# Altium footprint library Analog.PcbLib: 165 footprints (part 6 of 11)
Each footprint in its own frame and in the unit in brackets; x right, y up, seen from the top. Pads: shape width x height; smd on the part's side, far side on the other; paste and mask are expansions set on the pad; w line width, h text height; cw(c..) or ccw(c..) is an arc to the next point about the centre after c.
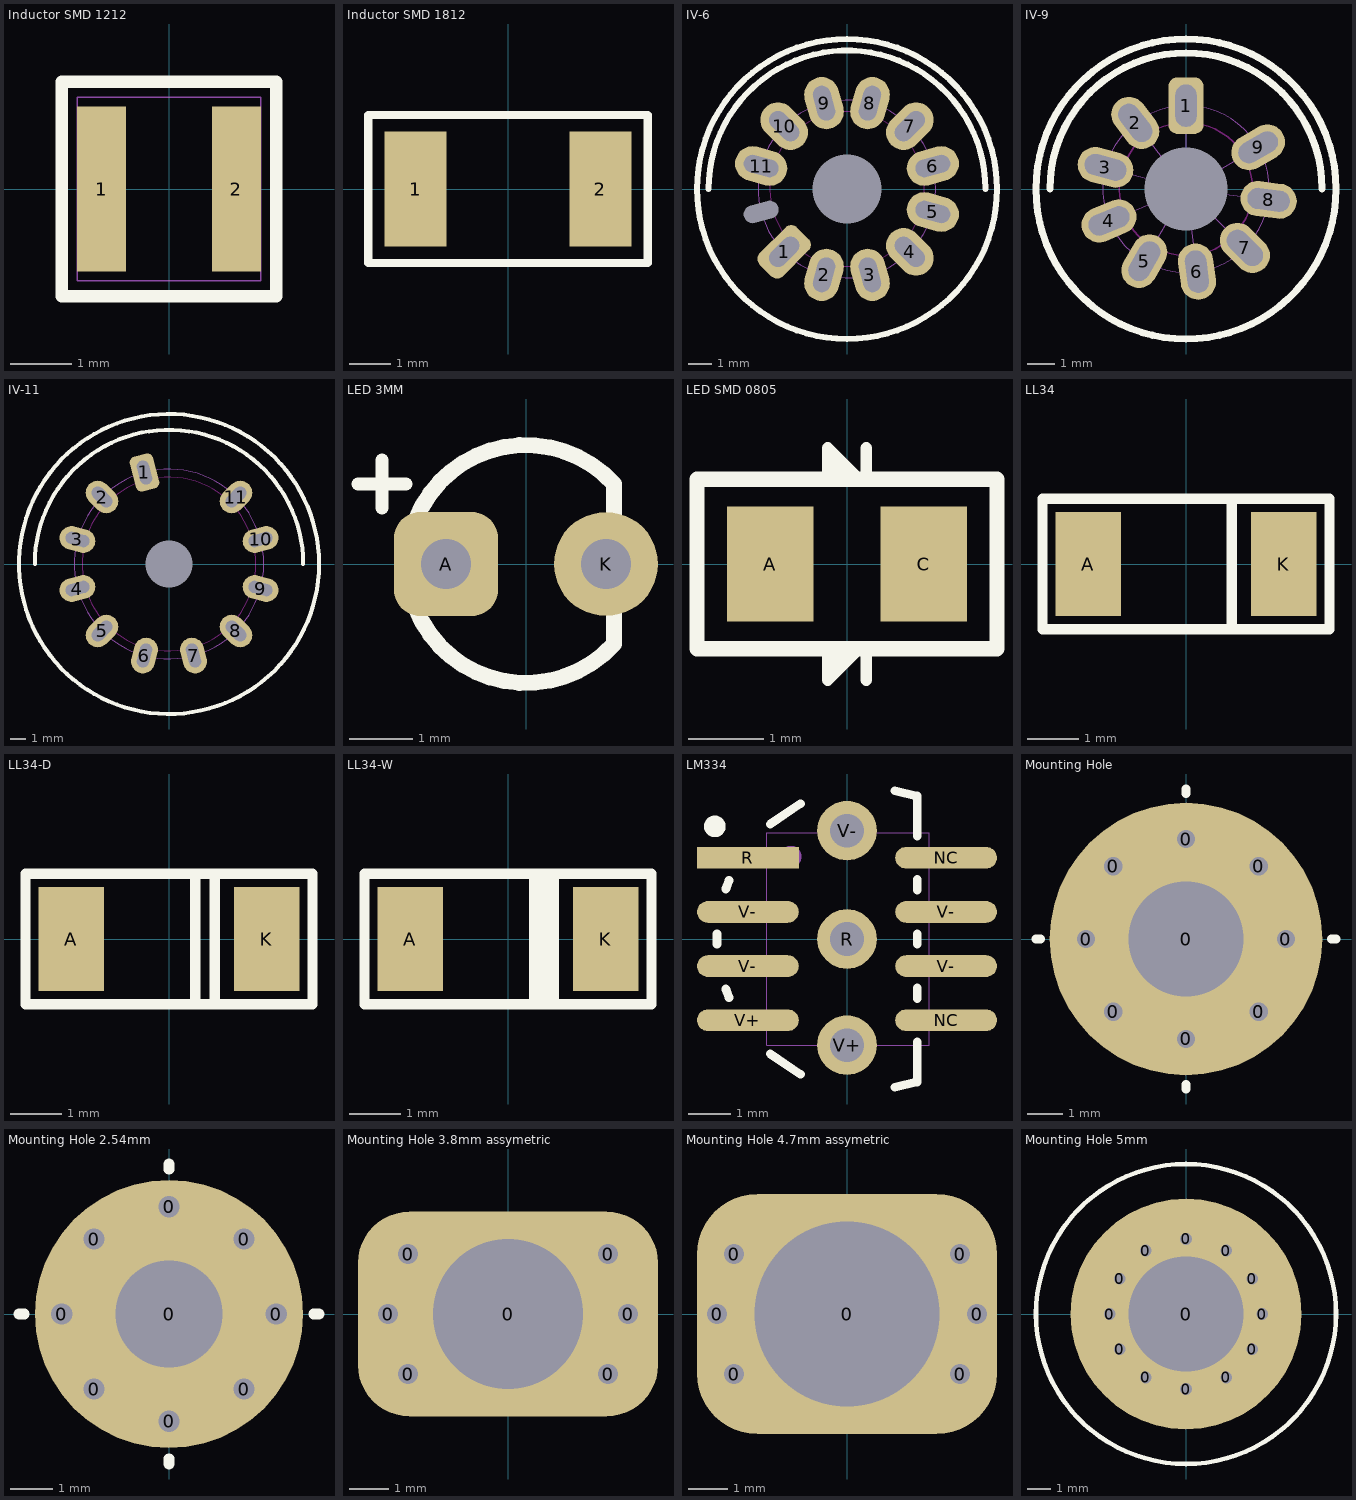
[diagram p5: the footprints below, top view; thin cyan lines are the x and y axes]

## Inductor SMD 1212 [mm]
pads (2):
  rect 0.8x2.7 smd: 1(-1.1,0) 2(1.1,0)
Top Overlay:
  lines w0.2: -1.75,-1.75 1.75,-1.75 1.75,1.75 -1.75,1.75 -1.75,-1.75
Mechanical 13:
  lines w0.025: -1.5,-1.5 1.5,-1.5 1.5,1.5 -1.5,1.5 -1.5,-1.5
  text ".Designator" at -1.475,-0.45 h1.02

## Inductor SMD 1812 [mm]
pads (2):
  rect 1.5x2.8 smd: 1(-2.25,0) 2(2.25,0)
Top Overlay:
  lines w0.2: -3.4,-1.8 -3.4,1.8 3.4,1.8 3.4,-1.8 -3.4,-1.8
Mechanical 13:
  lines w0.025: -3.4,-1.8 -3.4,1.8 3.4,1.8 3.4,-1.8 -3.4,-1.8
  text ".Designator" at -2.794,-0.483 h1.02

## IV-6 [mil] "IV-6 VFD"
height 1574.8
pads (13):
  round 0 hole 118.11 unplated: 0(0,0)
  rrect50% 90x56 hole 30 slot 60 at 45 deg rot 45: 1(-107.17,-107.17)
  oval 90x60 hole 30 slot 60 at 75 deg rot 75: 2(-39.21,-146.42) 8(39.21,146.42)
  oval 90x60 hole 30 slot 60 at 105 deg rot 105: 3(39.21,-146.42) 9(-39.21,146.42)
  oval 90x60 hole 30 slot 60 at 135 deg rot 135: 4(107.17,-107.17) 10(-107.17,107.17)
  oval 90x60 hole 30 slot 60 at 165 deg rot 165: 5(146.42,-39.21) 11(-146.42,39.21)
  oval 90x60 hole 30 slot 60 at 15 deg rot 15: 6(146.42,39.21)
  oval 90x60 hole 30 slot 60 at 45 deg rot 45: 7(107.17,107.17)
  round 0 hole 30 slot 60 at 15 deg: 12(-146.42,-39.21)
Top Overlay:
  circle w10: c0,0 r255.91
  lines w10: -236.22,0 cw(c0,0) 236.22,0
Bottom Overlay:
  lines w8: -19.68,200.79 0,181.1 ; 0,255.91 0,181.1 ; 19.68,200.79 0,181.1
Keep-Out Layer:
  circle w2: c0,0 r131.89
Mechanical 13:
  circle w1: c0,0 r151.57

## IV-9 [mil] "IV-9 Numitron"
height 1377.95
pads (10):
  round 0 hole 118.11 unplated: 0(0,0)
  rrect50% 50x80 hole 30 slot 60 at 90 deg: 1(0,118.11)
  oval 50x80 hole 30 slot 60 at 127.5 deg rot 37.5: 2(-71.89,93.7)
  oval 50x80 hole 30 slot 60 at 165 deg rot 75: 3(-114.09,30.55)
  oval 50x80 hole 30 slot 60 at 22.5 deg rot 112.5: 4(-109.13,-45.2)
  oval 50x80 hole 30 slot 60 at 60 deg rot 150: 5(-59.06,-102.28)
  oval 50x80 hole 30 slot 60 at 97.5 deg rot 7.5: 6(15.43,-117.1)
  oval 50x80 hole 30 slot 60 at 135 deg rot 45: 7(83.52,-83.52)
  oval 50x80 hole 30 slot 60 at 172.5 deg rot 82.5: 8(117.1,-15.42)
  oval 50x80 hole 30 slot 60 at 30 deg rot 120: 9(102.28,59.06)
Top Overlay:
  circle w10: c0,0 r212.6
  lines w10: -192.91,0 cw(c0,0) 192.91,0
Keep-Out Layer:
  circle w2: c0,0 r94.49
Mechanical 13:
  circle w1: c0,0 r118.11
  lines w1: -114.08,30.57 0,0 ; -109.12,-45.2 0,0 ; -71.9,93.7 0,0 ; -59.06,-102.29 0,0 ; 0,118.11 0,0 ; 15.42,-117.1 0,0 ; 83.52,-83.52 0,0 ; 102.29,59.06 0,0 ; 117.1,-15.42 0,0

## IV-11 [mil] "IV-11 VFD"
height 2362.2
pads (12):
  round 0 hole 118.11 unplated: 0(0,0)
  rrect50% 90x60 hole 30 slot 60 at 105 deg rot 105: 1(-61.14,228.17)
  oval 90x60 hole 30 slot 60 at 135 deg rot 135: 2(-167.05,167.05) 8(167.05,-167.05)
  oval 90x60 hole 30 slot 60 at 165 deg rot 165: 3(-228.19,61.14) 9(228.19,-61.14)
  oval 90x60 hole 30 slot 60 at 15 deg rot 15: 4(-228.19,-61.14) 10(228.19,61.14)
  oval 90x60 hole 30 slot 60 at 45 deg rot 45: 5(-167.05,-167.05) 11(167.05,167.05)
  oval 90x60 hole 30 slot 60 at 75 deg rot 75: 6(-61.14,-228.19)
  oval 90x60 hole 30 slot 60 at 105 deg rot 105: 7(61.14,-228.19)
Top Overlay:
  circle w10: c0,0 r374.02
  lines w10: -334.65,0 cw(c0,0) 334.65,0
Bottom Overlay:
  lines w8: -19.68,259.84 0,240.16 ; 0,314.96 0,240.16 ; 19.68,259.84 0,240.16
Keep-Out Layer:
  circle w2: c0,0 r216.54
Mechanical 13:
  circle w1: c0,0 r236.22

## LED 3MM [mil]
height 220
pads (2):
  rrect50% 65x65 hole 31: A(-50,0)
  round 65 hole 31: K(50,0)
Top Overlay:
  lines w8: -105,50 -75,50 ; -90,35 -90,65
  lines w10: 55,-50 cw(c0,0) 55,50 55,-50

## LED SMD 0805 [mil]
pads (2):
  rect 45x60 smd: A(-40,0) C(40,0)
Top Overlay:
  region: -10,44.31 6,44.31 -10,60.31
  region: -10,-44.31 6,-44.31 -10,-60.31
  lines w6: -10,-44.31 -10,-60.31 6,-44.31 ; -10,44.31 -10,60.31 6,44.31 ; 10,-60.31 10,-44.31 ; 10,44.31 10,60.31
  lines w8: -78,-44 78,-44 78,44 -78,44 -78,-44
Mechanical 13:
  lines w1: -78,-44 -78,44 78,44 78,-44 -78,-44
  text ".Designator" at -70,-19 h40

## LL34 [mil]
pads (2):
  rect 50x80 smd: A(-75,0) K(75,0)
Top Overlay:
  lines w8: 35,-50 35,50 ; -110,-50 110,-50 110,50 -110,50 -110,0 -110,-50
Mechanical 13:
  lines w1: 35,-50 35,50 ; -110,-50 110,-50 110,50 -110,50 -110,-50
  text ".Designator" at -99,-18 h40

## LL34-D [mil]
pads (2):
  rect 50x80 smd: A(-75,0) K(75,0)
Top Overlay:
  lines w8: 20,-50 20,50 ; 35,-50 35,50 ; -110,-50 110,-50 110,50 -110,50 -110,0 -110,-50
Mechanical 13:
  lines w1: 20,-50 20,50 ; 35,-50 35,50 ; -110,-50 -110,50 110,50 110,-50 -110,-50
  text ".Designator" at -100,-19 h40

## LL34-W [mil]
pads (2):
  rect 50x80 smd: A(-75,0) K(75,0)
Top Overlay:
  lines w8: 20,-50 20,50 ; 25,-50 25,50 ; 30,-50 30,50 ; 35,-50 35,50 ; -110,-50 -110,0 -110,50 110,50 110,-50 -110,-50
Mechanical 13:
  lines w1: 20,-50 20,50 ; 25,-50 25,50 ; 30,-50 30,50 ; 35,-50 35,50 ; -110,-50 -110,50 110,50 110,-50 -110,-50
  text ".Designator" at -99,-18 h40

## LM334 [mil]
pads (11):
  oval 94x20 smd: NC(91.5,-75) NC(91.5,75) V+(-91.5,-75) V-(-91.5,-25) V-(-91.5,25) V-(91.5,-25) V-(91.5,25)
  rect 94x20 smd: R(-91.5,75)
  round 55 hole 31: R(0,0) V+(0,-98) V-(0,100)
Top Overlay:
  circle w10: c-122,104 r5
  lines w8: -120,-5 -120,5 ; -112,-46 -109,-54 ; -112,46 -109,54 ; -71,-106 -43,-125 ; -71,106 -43,125 ; 44,-136.8 65,-132 ; 44,136.8 65,132 65,95 ; 65,-131 65,-95 ; 65,-55 65,-45 ; 65,-5 65,5 ; 65,45 65,55
Mechanical 13:
  circle w10: c-52,76 r5
  lines w1: -74,-98 -74,98 76,98 76,-98 -74,-98
  text ".Designator" at 14,87 h40

## Mounting Hole [mil]
pads (9):
  round 34 hole 20: 0(-110,0) 0(-80,-80) 0(-80,80) 0(0,-110) 0(0,110) 0(80,-80) 0(80,80) 0(110,0)
  round 300 hole 126: 0(0,0)
Top Overlay:
  lines w10: -165,0 -160,0 ; 0,-165 0,-160 ; 0,160 0,165 ; 160,0 165,0

## Mounting Hole 2.54mm [mil]
pads (9):
  round 34 hole 20: 0(-100,0) 0(-70,-70) 0(-70,70) 0(0,-100) 0(0,100) 0(70,-70) 0(70,70) 0(100,0)
  round 250 hole 100: 0(0,0)
Top Overlay:
  lines w10: -140,0 -135,0 ; 0,-140 0,-135 ; 0,135 0,140 ; 135,0 140,0

## Mounting Hole 3.8mm assymetric [mil]
pads (7):
  round 34 hole 20: 0(-120,0) 0(-100,-60) 0(-100,60) 0(100,-60) 0(100,60) 0(120,0)
  rrect50% 300x204.72 hole 149.61: 0(0,0)

## Mounting Hole 4.7mm assymetric [mil]
pads (7):
  round 34 hole 20: 0(-130,0) 0(-113,-60) 0(-113,60) 0(113,-60) 0(113,60) 0(130,0)
  rrect50% 300x240 hole 185: 0(0,0)

## Mounting Hole 5mm [mil]
pads (13):
  round 34 hole 20: 0(-130,0) 0(-113,-60) 0(-113,60) 0(-68.9,-108.27) 0(-68.9,108.27) 0(0,-127.95) 0(0,127.95) 0(68.9,-108.27) 0(68.9,108.27) 0(113,-60) 0(113,60) 0(130,0)
  round 393.7 hole 196.85: 0(0,0)
Top Overlay:
  circle w7.87: c0,0 r255.91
